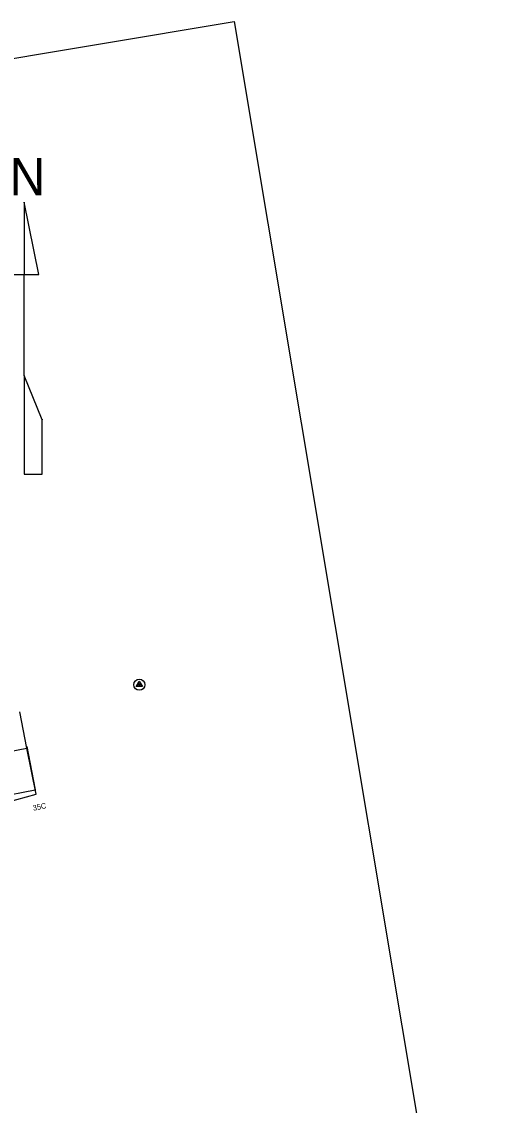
# Model space of a CAD drawing. Extents: x 1509010 to 1513406, y 898655 to 900162.
# Drawn here: x 1511482 to 1511742, y 899577 to 900162 of the extents above; entities that cross this region are included whole.
import ezdxf

# ---------------------------------------------------------------- set-up
doc = ezdxf.new("R2010")
doc.units = 0
for name, color, linetype in [('CO_Control_Temp', 7, 'Continuous'), ('RD_EX_Misc', 7, 'Continuous'), ('RD_HC_Survey', 7, 'Continuous'), ('RD_PD_CstnLmt', 7, 'Continuous'), ('RD_PD_CstnLmt_TX', 7, 'Continuous'), ('RD_PD_Final_TrvlWay', 7, 'Continuous'), ('RD_PD_RW', 7, 'Continuous'), ('RD_Sketch2', 7, 'Continuous')]:
    doc.layers.add(name, color=color, linetype=linetype)

# ---------------------------------------------------------------- blocks, each defined once
blk = doc.blocks.new('NA')
at = {"layer": 'RD_EX_Misc'}
for p, q in [((7.92, 31.07), (0.08, 70.27)), ((0.08, 70.27), (0.08, 70.27)), ((0.08, 70.27), (0.08, 31.07)), ((-7.76, 31.07), (0.08, 31.07)), ((0.08, -23.33), (0.08, 31.07)), ((0.08, 31.07), (7.92, 31.07)), ((7.92, 31.07), (7.92, 31.54)), ((9.88, -47.33), (0.08, -23.33)), ((0.08, -23.33), (0.08, -76.73)), ((9.88, -76.73), (9.88, -47.06)), ((9.88, -47.06), (9.88, -47.33)), ((0.08, -76.73), (9.88, -76.73))]:
    blk.add_line(p, q, dxfattribs=at)
blk.add_text('N', height=20, dxfattribs=at).set_placement((-7.81, 73.98))

msp = doc.modelspace()

# ---------------------------------------------------------------- linework, layer by layer
at = {"layer": 'CO_Control_Temp'}
for p, q in [((1511544.1, 899803.15), (1511545.84, 899806.15)), ((1511545.84, 899806.15), (1511547.57, 899803.15)), ((1511547.57, 899803.15), (1511544.1, 899803.15)), ((1511545.84, 899804.15), (1511545.84, 899804.15))]:
    msp.add_line(p, q, dxfattribs=at)
msp.add_circle((1511545.84, 899804.15), 1, dxfattribs=at)
at = {"layer": 'RD_HC_Survey'}
for radius in [3, 0.282]:
    msp.add_circle((1511545.84, 899804.15), radius, dxfattribs=at)
at = {"layer": 'RD_PD_CstnLmt'}
for p, q in [((1511490.03, 899745.13), (1511485.12, 899769.99)), ((1511441.69, 899731.84), (1511490.03, 899745.13))]:
    msp.add_line(p, q, dxfattribs=at)
at = {"layer": 'RD_PD_Final_TrvlWay'}
for p, q in [((1511485.12, 899769.99), (1511481.25, 899789.61)), ((1511094.81, 899692.91), (1511485.12, 899769.99))]:
    msp.add_line(p, q, dxfattribs=at)
at = {"layer": 'RD_PD_RW'}
for p in [(1511484.96, 899770.81), (1511182.65, 899686.82)]:
    msp.add_line(p, (1511489.58, 899747.42), dxfattribs=at)
at = {"layer": 'RD_Sketch2'}
msp.add_lwpolyline([(1510176.81, 899925.26), (1511597.17, 900162.3), (1511742.02, 899294.3), (1510321.67, 899057.27)], close=True, dxfattribs=at)

# ---------------------------------------------------------------- block references
at = {"layer": 'RD_Sketch2', "rotation": 4.034374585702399e-11}
msp.add_blockref('NA', (1511483.52, 899994.6), dxfattribs=at)

# ---------------------------------------------------------------- texts
at = {"layer": 'RD_PD_CstnLmt_TX'}
msp.add_text('35C', height=3, rotation=11.17037, dxfattribs=at).set_placement((1511488.56, 899736.07))

doc.saveas('drawing.dxf')
